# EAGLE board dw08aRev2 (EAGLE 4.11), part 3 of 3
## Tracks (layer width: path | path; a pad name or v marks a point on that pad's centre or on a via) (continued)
I_MB03  (via drill 0.61) (continued)
  Bottom 0.152: v220.09,95.89 221.23,95.89 235.97,110.62 237.36,110.62 239.01,112.27 A06.J1 | v285.75,52.2 285.75,52.96 v306.58,73.79 | v303.53,96.9 303.53,97.03 v306.58,100.08 | v292.61,114.05 292.1,114.05 291.21,113.16 A02.J1 | v267.59,138.68 268.86,139.95 266.32,142.49 253.49,142.49 249.81,138.81 249.81,138.18 242.19,130.56 240.92,130.56 224.16,113.79 220.09,113.79 208.41,102.11 208.41,100.71 A08.N2
I_MB03\  (via drill 0.61)
  Top 0.152: v222.76,101.98 219.33,105.41 218.69,105.41 211.58,112.52 211.58,115.19 A08.H2 | v304.17,32 294.13,42.04 294.13,45.34 B02.H1 | v287.4,12.7 265.18,12.7 259.08,18.8 258.95,18.8 258.57,19.18 258.57,19.81 253.11,25.27 252.6,25.27 249.81,28.07 247.65,28.07 v247.4,28.32 | v243.84,28.32 243.21,28.32 v223.52,48.01 | v244.86,68.71 244.86,70.36 243.59,71.63 242.95,71.63 v234.82,79.76 | v231.39,79.76 224.16,87 224.16,88.27 v217.17,95.25 | v279.53,132.84 293.24,119.13 293.24,116.59 A02.H1
  Bottom 0.152: v304.17,32 304.17,30.86 304.42,30.61 304.42,29.72 v287.4,12.7 | v243.84,28.32 v247.4,28.32 | v223.52,48.01 223.65,48.01 232.79,57.15 233.3,57.15 v244.86,68.71 | v234.82,79.76 v231.39,79.76 | v217.17,95.25 217.55,95.25 221.74,99.44 221.74,100.84 222.5,101.6 v222.76,101.98 226.82,101.98 235.84,111 236.35,111 239.14,113.79 239.78,113.79 242.19,116.2 A06.H1 243.59,116.33 245.24,117.98 246.63,117.98 252.98,124.33 259.33,124.33 260.86,125.86 262.76,125.86 269.75,132.84 v279.53,132.84
I_MB04  (via drill 0.61)
  Top 0.152: v298.45,42.8 298.45,43.69 284.1,58.04 284.1,58.17 283.46,58.8 283.46,59.56 283.08,59.94 283.08,61.34 279.91,64.52 279.91,65.02 276.61,68.33 276.1,68.33 260.86,83.57 260.86,85.85 260.22,86.49 260.22,87.5 v257.3,90.42 246.63,101.09 245.24,101.09 243.59,102.74 A06.M1 | v281.69,111.63 282.7,110.62 287.91,110.62 293.24,105.28 293.24,103.89 A02.M1 | v200.79,117.22 200.91,117.22 202.44,115.7 202.82,115.7 210.44,108.08 214.25,108.08 220.73,101.6 221.49,101.6 222.25,100.84 222.76,100.84 227.33,96.27 227.46,96.27 v229.74,93.98
  Bottom 0.152: v298.45,42.8 294.13,38.48 294.13,34.04 B02.M1 | v281.69,111.63 281.43,111.63 275.08,105.28 272.54,105.28 272.16,104.9 271.78,104.9 v257.3,90.42 | v200.79,117.22 199.9,116.33 199.14,116.33 A09.H2 | v229.74,93.98 230.89,93.98 236.09,99.19 237.24,99.19 239.14,101.09 240.54,101.09 242.19,102.74 A06.M1
I_MB04\  (via drill 0.61)
  Top 0.152: v213.23,83.44 212.98,83.69 211.84,83.69 A08.U2 | v227.08,95.5 235.97,86.61 236.35,86.61 250.06,72.9 251.33,72.9 261.62,62.61 263.02,62.61 264.03,61.59 264.03,61.34 288.42,36.96 289.81,36.96 B02.L1 | v296.93,114.3 296.93,116.2 296.55,116.59 296.55,116.97 v276.48,137.03 | v241.94,118.24 240.28,116.59 v244.47,112.39
  Bottom 0.152: v213.23,83.44 214.63,83.44 226.31,95.12 226.82,95.12 227.2,95.5 | 227.2,95.5 235.97,104.27 237.36,104.27 239.01,105.92 A06.L1 240.16,107.06 241.81,108.71 241.81,110.11 244.09,112.39 v244.47,112.39 | 227.2,95.5 v227.08,95.5 | v296.93,114.3 296.8,114.3 290.96,108.46 290.96,107.06 A02.L1 | v276.48,137.03 265.18,137.03 264.67,136.53 260.86,136.53 253.11,128.78 252.48,128.78 v241.94,118.24
I_MB05  (via drill 0.61)
  Top 0.152: v215.14,69.47 200.91,83.69 199.14,83.69 A09.U2 | v240.92,92.33 241.05,92.33 A06.S1 | v230.5,81.79 251.33,60.96 251.33,60.83 v255.4,56.77 258.83,53.34 258.83,52.83 270.51,41.15 270.89,41.15 290.96,21.08 292.99,21.08 B02.S1 | v290.32,92.08 291.46,90.93 292.99,90.93 A02.S1
  Bottom 0.152: v215.14,69.47 218.06,69.47 230.38,81.79 | 230.38,81.79 v240.92,92.33 | 230.38,81.79 v230.5,81.79 | v290.32,92.08 290.32,91.69 v255.4,56.77
I_MB05\  (via drill 0.61)
  Top 0.152: v277.75,45.85 285.12,38.48 285.12,37.85 293.24,29.72 293.24,27.69 B02.P1 | v282.57,52.32 282.57,53.59 264.16,72.01 | 264.16,72.01 257.05,79.12 255.78,79.12 255.14,79.76 255.14,80.64 249.68,86.11 249.68,87.12 250.32,87.76 244.98,93.09 244.98,94.49 243.33,96.14 A06.P1 | v292.1,100.33 293.24,99.19 293.24,97.54 A02.P1 | v264.16,71.37 264.16,72.01 | v194.56,96.77 194.56,96.01 209.04,81.53 209.04,79.63 209.8,78.87 216.53,78.87 v227.58,67.82 | v242.44,81.79 242.95,81.79 248.16,76.58 251.08,76.58 259.08,68.58 259.08,67.82 v259.84,67.06
  Bottom 0.152: v277.75,45.85 277.75,47.5 v282.57,52.32 | v292.1,100.33 292.1,99.69 288.67,96.27 288.67,95.38 265.94,72.64 265.43,72.64 v264.16,71.37 264.03,70.99 260.1,67.06 v259.84,67.06 | v194.56,96.77 194.82,97.03 194.82,99.31 A09.N2 | v227.58,67.82 227.71,67.82 232.28,72.39 232.28,72.77 233.55,74.04 234.7,74.04 v242.44,81.79
I_MB06  (via drill 0.61)
  Top 0.152: v197.87,86.11 196.34,87.63 196.34,87.88 184.66,99.57 183.26,99.57 A10.N2 | v250.44,86.49 256.03,80.9 256.29,80.9 284.23,52.96 286.13,52.96 286.26,52.83 286.64,52.83 B02.E2 | v267.46,140.21 267.72,140.21 283.59,124.33 284.99,124.33 286.64,122.68 A02.E2
  Bottom 0.152: v197.87,86.11 218.69,106.93 219.07,106.93 221.62,109.47 222.12,109.47 232.79,120.14 234.19,120.14 235.84,121.79 A06.E2 236.98,122.94 236.98,124.33 242.32,129.67 246,129.67 249.81,133.48 250.06,133.48 250.95,134.37 252.35,134.37 255.65,137.67 263.52,137.67 263.91,138.05 265.3,138.05 v267.46,140.21 | v250.44,86.49 250.44,87 260.99,97.54 260.99,98.3 266.32,103.63 266.57,103.63 272.42,109.47 272.92,109.47 283.59,120.14 284.99,120.14 286.64,121.79 A02.E2
I_MB06\  (via drill 0.61)
  Top 0.152: v196.85,103.12 186.18,113.79 186.18,115.19 A10.H2 | v224.28,131.19 225.43,131.19 226.31,130.3 226.82,130.3 229.62,127.51 231.01,127.51 232.66,125.86 A06.D2 | v280.54,62.74 281.43,61.85 281.43,61.34 282.07,60.71 282.07,59.69 283.72,58.04 283.72,56.26 B02.D2 | v305.94,95.25 305.94,95.63 v300.99,100.58 | v303.78,104.14 292.61,115.32 292.61,118.62 287.91,123.32 286.51,123.32 284.86,124.97 A02.D2 283.72,126.11 282.07,127.76 282.07,129.16 270.26,140.97 v266.45,140.97 | v249.05,138.56 v252.98,138.56
  Bottom 0.152: v196.85,103.12 196.85,103.76 v224.28,131.19 | v280.54,62.74 280.54,62.99 282.07,64.52 282.07,64.9 293.24,76.07 293.62,76.07 304.29,86.74 304.29,93.6 v305.94,95.25 | v300.99,100.58 300.99,101.35 v303.78,104.14 | v249.05,138.56 241.43,130.94 240.79,130.94 235.71,125.86 234.06,125.86 A06.D2 | v252.98,138.56 264.03,138.56 v266.45,140.97
I_MB07  (via drill 0.61)
  Top 0.152: v241.17,114.05 233.55,121.67 232.41,121.67 224.41,129.67 224.03,129.67 223.52,130.18 223.52,130.56 218.06,136.02 216.92,136.02 216.15,135.25 215.14,136.27 213.87,136.27 v209.42,140.72 | v285.88,38.35 285.88,38.86 276.61,48.13 276.35,48.13 v262.64,61.85 | v297.43,97.54 297.43,97.79 289.43,105.79 289.43,107.19 287.78,108.84 A02.K2 | v242.32,106.17 239.4,109.09 237.24,109.09 A06.K2 | v268.22,130.18 268.22,132.21 263.52,136.91 263.52,137.67 266.06,140.21 266.83,139.45 267.97,139.45 283.46,123.95 283.72,123.95 v290.96,116.71
  Bottom 0.152: v241.17,114.05 240.79,113.67 240.79,112.14 238.63,109.98 237.24,109.98 A06.K2 | v209.42,140.72 200.79,140.72 199.52,139.45 198.88,139.45 179.2,119.76 178.56,119.76 176.78,117.98 175.39,117.98 173.74,116.33 A11.H2 | v285.88,38.35 286.64,39.12 286.77,39.12 B02.K2 | v262.64,61.85 262.64,62.74 v297.43,97.54 | v242.32,106.17 243.46,106.17 249.81,112.52 250.57,112.52 v268.22,130.18 | v290.96,116.71 290.96,114.81 289.43,113.28 289.43,111.89 287.78,110.24 A02.K2
I_MB07\  (via drill 0.61)
  Top 0.152: v192.15,81.53 189.99,83.69 186.44,83.69 A10.U2 | v223.14,112.14 224.03,112.14 v227.58,108.58 | v255.91,80.14 256.54,79.5 257.18,79.5 286.89,49.78 286.89,46.74 B02.H2 | v231.27,112.27 231.52,112.27 v259.46,84.33
  Bottom 0.152: v192.15,81.53 197.49,86.87 198.12,86.87 221.49,110.24 221.49,110.49 v223.14,112.14 | v227.58,108.58 v231.27,112.27 232.79,113.79 234.19,113.79 235.84,115.44 A06.H2 | v255.91,80.14 255.91,80.64 259.59,84.33 | 259.59,84.33 272.92,97.66 272.92,99.06 284.1,110.24 284.1,111 285.24,112.14 285.24,113.54 286.89,115.19 A02.H2 | v259.46,84.33 259.59,84.33
I_MB08  (via drill 0.61)
  Top 0.152: v286.89,29.59 286.89,31.5 v265.81,52.58 | v294.26,81.03 294.26,81.28 293.62,81.92 293.62,82.55 286.26,89.92 286.26,93.09 v285.75,93.6 | v191.39,100.33 191.39,101.09 v190.63,101.85 | v209.93,123.32 211.84,123.32 217.3,117.86 219.46,117.86 229.24,108.08 229.24,107.57 230,106.81 230,105.03 234.44,100.58 234.44,99.19 236.09,97.54 A06.P2 | v263.91,1.27 237.24,1.27 v229.11,9.4 | v219.46,1.27 217.42,3.3 216.79,3.3 215.65,4.45 213.74,4.45 208.91,9.27 208.15,9.27 203.71,13.72 203.71,17.91 v190.37,31.24 | v196.22,41.53 196.22,42.16 196.34,42.29 196.34,45.21 195.2,46.35 194.56,46.35 v165.99,74.93
  Bottom 0.152: v286.89,29.59 286.89,27.69 B02.P2 286.64,26.54 283.85,26.54 262.89,5.59 262.89,2.29 v263.91,1.27 | v265.81,52.58 v294.26,81.03 | v285.75,93.6 285.75,95 286.89,96.14 A02.P2 | v191.39,100.33 175.64,84.58 173.74,84.58 A11.U2 172.59,83.44 170.94,81.79 170.94,80.39 165.99,75.44 v165.99,74.93 | v190.63,101.85 192.41,101.85 209.04,118.49 209.04,122.43 v209.93,123.32 | v229.11,9.4 227.58,9.4 v219.46,1.27 | v190.37,31.24 190.37,35.69 v196.22,41.53
I_MB08\  (via drill 0.61)
  Top 0.152: v276.23,47.37 276.86,46.74 276.86,45.59 286.89,35.56 286.89,34.04 B02.M2 | v288.16,60.71 268.22,80.64 268.22,81.41 268.73,81.92 269.24,81.92 269.75,81.41 269.75,81.03 270.89,79.88 273.05,79.88 274.19,81.03 270.89,84.33 270.26,84.33 v268.61,85.98 268.22,85.85 263.78,85.85 v261.62,88.01 | v203.2,129.79 208.28,129.79 232.79,105.28 234.19,105.28 235.84,103.63 A06.M2 237.24,102.74 237.74,102.23 v238.38,102.23 | v263.52,90.42 263.52,90.81 263.02,91.31 263.02,92.46 258.19,97.28 258.19,97.79 249.43,106.55 247.78,106.55 v246.38,107.95
  Bottom 0.152: v276.23,47.37 276.23,49.28 286.77,59.82 287.27,59.82 v288.16,60.71 | v268.61,85.98 268.61,86.11 274.07,91.57 275.21,91.57 276.73,93.09 276.73,94.23 283.59,101.09 284.99,101.09 286.64,102.74 A02.M2 | v203.2,129.79 173.86,100.46 170.56,100.46 A11.N2 | v261.62,88.01 261.62,88.52 v263.52,90.42 | v246.38,107.95 245.75,107.95 243.59,105.79 243.08,105.79 242.7,105.41 241.55,105.41 v238.38,102.23
I_MB09  (via drill 0.61)
  Top 0.152: v217.55,71.88 212.34,77.09 208.03,77.09 181.23,103.89 180.34,103.89 178.94,105.28 175.64,105.28 173.74,107.19 172.47,107.19 165.23,114.43 163.58,114.43 162.56,115.44 161.04,115.44 A12.H2 | v284.61,19.56 280.42,19.56 248.16,51.82 248.16,52.32 247.27,53.21 | 247.27,53.21 246.38,53.21 246.13,53.47 245.49,53.47 224.28,74.68 224.28,75.31 v223.52,76.07 | 247.27,53.21 v247.27,53.98
  Bottom 0.152: v217.55,71.88 219.58,71.88 223.65,75.95 | 223.65,75.95 229.74,82.04 229.74,82.17 230.63,83.06 230.76,83.06 234.44,86.74 234.44,88.14 236.09,89.79 A06.S2 | v284.61,19.56 285.24,20.19 286.64,20.19 B02.S2 | 223.65,75.95 v223.52,76.07 | v247.27,53.98 259.59,66.29 260.22,66.29 283.97,90.04 286.64,90.04 A02.S2
I_MB10  (via drill 0.61)
  Top 0.152: v160.91,98.42 160.53,98.81 159.51,98.81 158.75,99.57 157.86,99.57 A12.N2 | v184.02,113.79 v220.73,77.09 221.11,77.34 245.36,53.09 246,53.09 246.25,52.83 246.38,52.83 v246.89,52.32 281.31,17.91 283.46,17.91 B02.T2
  Bottom 0.152: v160.91,98.42 165.61,98.42 165.86,98.68 166.12,98.68 176.53,109.09 177.29,109.09 181.99,113.79 v184.02,113.79 | v220.73,77.09 220.73,77.34 221.36,77.98 221.36,78.61 228.22,85.47 231.27,85.47 232.66,86.87 A06.T2 | v246.89,52.32 282.07,87.5 283.46,87.5 A02.T2
I_MB11  (via drill 0.61)
  Top 0.152: 267.21,45.47 290.96,21.72 294.26,21.72 296.04,19.94 296.04,18.29 289.31,11.56 284.86,11.56 B02.V2 | 267.21,45.47 267.21,49.91 233.55,83.57 232.79,83.57 231.9,82.68 | 231.9,82.68 232.92,81.66 A06.V2 | v189.48,58.55 187.2,60.83 181.99,60.83 160.78,82.04 160.78,83.44 A12.U2 | v224.92,87.38 224.92,87.25 228.22,83.95 228.73,83.95 229.62,83.06 231.52,83.06 231.9,82.68 | v259.59,53.21 259.59,53.09 267.21,45.47
  Bottom 0.152: v189.48,58.55 190.25,58.55 194.69,62.99 199.52,62.99 202.82,66.29 203.84,66.29 v224.92,87.38 | v259.59,53.21 259.71,53.21 280.04,73.53 280.04,74.17 282.45,76.58 282.45,77.09 284.35,78.99 284.35,80.26 A02.V2
I_MBINCR  (via drill 0.61)
  Top 0.152: v65.15,61.59 67.82,58.93 67.82,56.26 B19.D2 | v142.24,138.05 161.04,138.05 165.86,133.22 166.75,133.22 172.47,127.51 178.31,127.51 194.56,111.25 195.07,111.25 203.45,102.87 203.45,102.23 223.01,82.68 223.01,82.42 231.52,73.91 232.28,73.91 233.17,74.8 v232.03,75.95 231.65,76.2 230.25,77.6 229.49,77.6 228.09,78.99 228.09,81.53 225.43,84.2 v225.43,84.33 | v247.14,89.15 247.78,89.15 v249.17,87.76 | v255.14,93.73 255.65,93.73 v260.1,89.28 | v243.59,2.79 240.66,2.79 v233.93,9.53 | v224.03,2.03 219.33,2.03 v209.17,12.19 | v199.01,1.91 197.74,1.91 197.61,2.03 196.47,2.03 188.47,10.03 188.34,10.03 176.91,21.46 176.91,21.59 175.77,22.73 175.64,22.73 v173.35,25.02 | v190.12,44.58 190.12,45.34 v189.36,46.1
  Bottom 0.152: v65.15,61.59 65.41,61.59 69.72,65.91 69.72,66.55 113.92,110.74 114.94,110.74 v142.24,138.05 | v232.03,75.95 232.28,75.95 235.08,78.74 235.84,78.74 242.32,85.22 242.57,85.22 243.08,85.72 243.08,85.98 245.49,88.39 246.38,88.39 v247.14,89.15 | v249.17,87.76 v255.14,93.73 | v260.1,89.28 260.1,88.9 259.21,88.01 A04.T2 | v243.59,2.79 251.33,10.54 251.33,11.68 256.67,17.02 258.06,17.02 B04.T2 | v233.93,9.53 231.52,9.53 v224.03,2.03 | v209.17,12.19 207.39,12.19 206.88,11.68 206.88,9.91 199.01,2.03 v199.01,1.91 | v173.35,25.02 173.35,25.65 189.99,42.29 189.99,44.45 v190.12,44.58 | v189.36,46.1 189.99,46.1 194.56,50.67 195.07,50.67 197.87,53.47 201.17,53.47 209.04,61.34 209.04,67.94 220.22,79.12 220.47,79.12 224.92,83.57 224.92,83.82 v225.43,84.33
I_RUN  (via drill 0.61)
  Top 0.152: v273.18,21.97 273.94,21.21 273.94,21.08 B03.S2 | v258.57,7.62 254.25,7.62 249.94,11.94 249.94,12.06 249.56,12.45 248.92,12.45 241.17,20.19 241.17,20.7 225.93,35.94 225.93,37.34 224.28,38.99 B07.K2 223.14,40.13 221.49,41.78 220.09,41.78 218.95,42.93 v220.47,44.45 | v164.21,73.53 166.24,73.53 v185.29,54.48 | v199.77,57.4 199.77,55.75 220.09,35.43 221.23,35.43 222.12,36.32 221.87,36.58 221.87,37.72 v221.74,37.85 | v272.92,88.27 272.92,87.63 v274.83,85.72 | v257.18,65.28 257.05,65.28 256.16,66.17 254.13,66.17 v249.56,70.74
  Bottom 0.152: v273.18,21.97 269.75,18.54 269.11,18.54 259.33,8.76 259.33,8.38 v258.57,7.62 | v164.21,73.53 155.45,64.77 155.45,64.39 137.54,46.48 135.64,46.48 B14.H2 | v185.29,54.48 192.53,54.48 194.69,56.64 197.61,56.64 198.37,57.4 v199.77,57.4 | v221.74,37.85 223.14,39.24 B07.K2 | v272.92,88.27 274.19,89.53 274.19,89.79 A03.S2 | v274.83,85.72 274.57,85.72 270.38,81.53 270.38,78.99 269.11,77.72 268.48,77.72 259.46,68.71 259.46,67.82 259.08,67.44 259.08,67.18 v257.18,65.28 | v249.56,70.74 249.56,70.1 237.11,57.66 234.31,57.66 233.43,56.77 232.92,56.77 225.93,49.78 225.93,49.28 223.9,47.24 223.27,47.24 v220.47,44.45
I_SKIP  (via drill 0.61)
  Top 0.152: v104.52,35.05 84.45,55.12 81.66,55.12 B18.D2 | v125.09,51.05 127.76,51.05 127.89,50.93 128.4,50.93 147.07,32.26 151.64,32.26 v151.76,32.13 | v162.43,38.48 172.09,38.48 172.34,38.23 172.72,38.23 197.74,13.21 200.41,13.21 v200.66,12.95 | v210.57,22.23 211.2,22.23 v231.01,2.41 | v255.02,25.02 255.91,25.02 258.19,22.73 259.59,22.73 v259.84,22.48 | v266.7,102.87 265.81,102.87 258.19,110.49 258.19,111.38 v252.86,116.71 | v254,119 254,125.98 243.59,136.4 242.32,136.4 241.94,136.78 241.94,137.03 v236.73,142.24 | v201.42,103.63 201.42,101.85 v213.74,89.53
  Bottom 0.152: v104.52,35.05 109.09,35.05 v125.09,51.05 | v151.76,32.13 156.08,32.13 v162.43,38.48 162.69,38.86 171.45,47.62 171.45,48.39 187.83,64.77 188.34,64.77 211.58,88.01 212.22,88.01 v213.74,89.53 | v200.66,12.95 201.29,12.95 v210.57,22.23 | v231.01,2.41 233.81,2.41 243.71,12.32 243.71,13.46 247.14,16.89 247.14,17.27 248.16,18.29 248.54,18.29 253.49,23.24 253.49,23.5 v255.02,25.02 | v259.84,22.48 265.18,27.81 265.18,28.57 272.54,35.94 272.54,37.34 274.19,38.99 B03.K2 | v266.7,102.87 267.21,103.38 267.21,103.76 272.54,109.09 273.94,109.09 A03.K2 | v252.86,116.71 252.86,117.86 v254,119 | v236.73,142.24 235.33,142.24 228.47,135.38 228.47,134.87 225.93,132.33 225.93,131.06 224.66,129.79 223.39,129.79 203.71,110.11 203.71,105.92 v201.42,103.63
I_TS1  (via drill 0.61)
  Top 0.152: v242.7,35.05 241.68,36.07 240.41,36.07 B06.L1 | v263.4,55.63 265.68,53.34 266.19,53.34 267.21,52.32 267.21,51.82 294.51,24.51 294.51,23.62 296.42,21.72 296.42,18.16 B01.T2
  Bottom 0.152: v242.7,35.05 242.7,35.69 246.25,39.24 246.63,39.24 259.84,52.45 259.97,52.45 260.35,52.83 260.35,53.34 263.02,56.01 | 263.02,56.01 268.1,61.09 268.61,61.09 275.84,68.33 276.48,68.33 286.77,78.61 286.77,78.87 293.12,85.22 294.51,85.22 296.16,86.87 A01.T2 | 263.02,56.01 v263.4,55.63
I_TS3  (via drill 0.61)
  Top 0.152: v292.23,16.38 288.93,16.38 271.65,33.66 271.4,33.66 264.67,40.39 263.65,40.39 256.29,47.75 255.52,47.75 252.98,50.29 v251.08,50.29 | v241.68,42.29 240.54,42.29 240.41,42.42 B06.J1 | v293.75,95 297.81,90.93 299.34,90.93 A01.S2
  Bottom 0.152: v292.23,16.38 296.04,20.19 299.34,20.19 B01.S2 | v241.68,42.29 244.47,45.09 245.87,45.09 v251.08,50.29 251.46,50.55 261.87,60.96 261.87,62.23 262.25,62.61 262.25,62.87 293.75,94.36 v293.75,95
I_TT_INST  (via drill 0.61)
  Top 0.152: v148.84,44.45 152.78,44.45 v170.31,26.92 | v196.85,50.67 197.36,50.67 v198.75,49.28 v216.79,31.24 | v269.37,19.3 270.76,17.91 B03.T2 | v256.67,6.86 252.86,6.86 248.41,11.3 248.41,11.68 234.19,25.91 233.43,25.91 227.58,31.75 226.57,31.75 224.54,33.78 B07.M2 | v247.4,63.75 247.14,63.75 v232.92,77.98
  Bottom 0.152: v148.84,44.45 143.26,38.86 142.11,38.86 133.86,30.61 132.46,30.61 B14.N2 | v170.31,26.92 171.32,26.92 194.69,50.29 196.47,50.29 v196.85,50.67 | v216.79,31.24 221.49,31.24 223.14,32.89 B07.M2 | v269.37,19.3 269.11,19.3 v256.67,6.86 | v247.4,63.75 247.65,64.01 249.81,64.01 259.84,74.04 259.84,74.68 265.05,79.88 265.68,79.88 267.97,82.17 267.21,82.93 267.21,84.71 267.72,85.22 268.99,85.22 270.64,86.87 270.76,86.87 A03.T2 | v232.92,77.98 229.49,77.98 225.55,74.04 224.79,74.04 215.9,65.15 214.63,65.15 v198.75,49.28
I_WCOV  (via drill 0.61)
  Top 0.152: v236.85,3.17 223.01,17.02 221.36,17.02 B07.T2 | v254.51,22.23 254.51,23.37 252.98,24.89 251.59,24.89 249.94,26.54 B05.P2 | v137.41,13.21 136.02,14.61 136.02,14.86 121.16,29.72 119.76,29.72 B15.N2 | v183.64,45.34 183.64,44.7 199.26,29.08 201.04,29.08 204.22,25.91 204.47,25.91 206.25,24.13 206.25,23.88 210.57,19.56 210.82,19.56 212.6,17.78 212.6,16.13 v215.14,13.59 | v230.5,114.3 232.28,112.52 232.28,112.14 247.14,97.28 248.54,97.28 A05.P2 | v195.83,75.56 195.83,74.04 v199.26,70.61
  Bottom 0.152: v236.85,3.17 240.54,3.17 245.11,7.75 245.11,8.51 247.14,10.54 247.14,10.79 248.79,12.45 249.05,12.45 253.49,16.89 253.49,18.41 254.38,19.3 254.38,22.1 v254.51,22.23 | v137.41,13.21 144.4,13.21 159.64,28.45 160.15,28.45 174.75,43.05 | 174.75,43.05 175.64,43.94 182.25,43.94 v183.64,45.34 | v215.14,13.59 216.92,15.37 218.31,15.37 219.96,17.02 B07.T2 | v230.5,114.3 230.5,113.67 214.12,97.28 214.12,96.9 213.74,96.52 213.74,94.74 200.53,81.53 200.53,80.26 v195.83,75.56 | v199.26,70.61 189.48,60.83 189.23,60.83 188.59,60.2 188.59,59.18 174.75,45.34 174.75,43.05
N$1  (via drill 0.61)
  Top 0.152: v213.49,47.5 v217.17,43.81 | v237.49,63.63 237.74,63.63 239.01,62.36 B06.B1
  Bottom 0.152: v213.49,47.5 212.47,46.48 211.84,46.48 B08.H2 | v217.17,43.81 217.68,43.81 v237.49,63.63
N$2  (via drill 0.61)
  Top 0.152: v210.19,29.21 209.68,29.72 208.66,29.72 B08.N2 | v237.62,56.01 239.14,54.48 240.54,54.48 242.19,52.83 B06.E1
  Bottom 0.152: v210.19,29.21 210.82,29.21 v237.62,56.01
N$3  (via drill 0.61)
  Top 0.152: v240.92,47.5 241.17,47.5 242.19,46.48 B06.H1
  Bottom 0.152: v240.92,47.5 240.79,47.5 210.69,17.4 211.46,16.64 211.58,16.64 211.96,16.26 211.96,15.49 211.58,15.11 211.58,14.99 B08.U2
N$4  (via drill 0.61)
  Top 0.152: v217.55,60.33 221.36,56.52 224.92,56.52 225.93,55.5 225.93,54.99 240.79,40.13 242.19,40.13 B06.K1
  Bottom 0.152: v217.55,60.33 214.38,60.33 202.18,48.13 200.79,48.13 199.14,46.48 B09.H2
N$5  (via drill 0.61)
  Top 0.152: v216.92,7.87 215.14,9.65 213.61,9.65 195.71,27.56 195.71,29.46 B09.N2
  Bottom 0.152: v216.92,7.87 220.22,7.87 240.54,28.19 240.54,29.34 240.79,29.59 240.79,30.99 242.44,32.64 B06.M1
N$6  (via drill 0.61)
  Top 0.152: v213.49,2.92 v200.28,16.13
  Bottom 0.152: v213.49,2.92 215.77,2.92 216.53,3.68 216.92,3.68 226.19,12.95 227.2,12.95 232.79,18.54 236.09,18.54 240.79,23.24 240.79,24.64 242.44,26.29 B06.P1 | v200.28,16.13 B09.U2
O_3CYCLE
  Top 0.152: B19.H2 70.99,46.74 70.99,50.67 63.63,58.04 63.63,63.37 62.87,64.14 62.87,65.15 47.75,80.26 47.75,80.77 32.26,96.27 32.26,108.2 32.89,108.84 A22.K2
O_AC00  (via drill 0.61)
  Top 0.152: v118.75,65.79 118.75,66.42 104.65,80.52 104.65,81.03 104.27,81.41 104.27,85.85 103.5,86.61 103.5,88.52 102.11,89.92 102.11,102.62 92.58,112.14 92.58,119.89 92.46,120.02 92.46,123.95 93.22,124.71 A17.D2
  Bottom 0.152: v118.75,65.79 109.22,56.26 109.22,53.09 B16.E2
O_AC01  (via drill 0.61)
  Top 0.152: v91.69,72.01 98.3,65.41 98.3,64.52 98.55,64.26 98.55,61.21 105.79,53.98 105.79,53.09 109.09,49.78 109.09,46.74 B16.H2 | v104.27,87 104.27,106.81 95.76,115.32 95.76,120.9 96.39,121.54 A17.E2
  Bottom 0.152: v91.69,72.01 91.69,74.42 v104.27,87
O_AC02  (via drill 0.61)
  Top 0.152: v109.35,43.43 109.35,40.39 B16.K2 | v136.91,73.53 136.91,74.42 131.95,79.38 131.7,79.38 127.51,83.57 127.51,86.87 100.58,113.79 99.19,113.79 97.54,115.44 A17.H2
  Bottom 0.152: v109.35,43.43 109.35,43.69 117.35,51.69 117.35,52.2 129.67,64.52 129.67,66.29 v136.91,73.53
O_AC03  (via drill 0.61)
  Top 0.152: v69.09,82.8 82.68,69.22 82.68,68.07 83.06,67.69 83.19,67.69 91.82,59.05 91.82,57.78 92.2,57.4 92.2,48.51 106.93,33.78 108.84,33.78 B16.M2
  Bottom 0.152: v69.09,82.8 71.75,82.8 94.74,105.79 94.74,107.19 96.39,108.84 A17.K2
O_AC04  (via drill 0.61)
  Top 0.152: v125.73,46.61 125.73,47.24 124.33,48.64 124.33,54.99 116.59,62.74 116.33,62.74 103.25,75.82 103.25,81.28 v90.81,93.73
  Bottom 0.152: v125.73,46.61 109.98,30.86 109.98,27.69 B16.P2 | v90.81,93.73 90.81,95.5 94.74,99.44 94.74,100.84 96.39,102.49 A17.M2
O_AC05  (via drill 0.61)
  Top 0.152: v121.67,34.92 121.67,37.72 109.86,49.53 109.86,50.42 98.93,61.34 98.93,64.39 98.68,64.64 98.68,66.67 v83.44,81.92
  Bottom 0.152: v121.67,34.92 109.98,23.24 109.98,21.34 B16.S2 | v83.44,81.92 83.57,81.92 94.74,93.09 94.74,94.49 96.39,96.14 A17.P2
O_AC06  (via drill 0.61)
  Top 0.152: v96.14,54.48 96.39,54.23 96.39,53.09 B17.E2 | v104.52,62.87 104.52,65.91 v90.3,80.14
  Bottom 0.152: v96.14,54.48 v104.52,62.87 | v90.3,80.14 90.3,81.79 91.95,83.44 91.95,83.95 94.74,86.74 94.74,88.14 96.39,89.79 A17.S2
O_AC07  (via drill 0.61)
  Top 0.152: v103.12,53.98 103.12,54.99 87.5,70.61 87.5,73.91 v85.72,75.69
  Bottom 0.152: v103.12,53.98 97.28,48.13 97.28,46.74 B17.H2 | v85.72,75.69 85.72,77.72 91.57,83.57 91.57,84.96 93.22,86.61 A17.T2
O_AC08  (via drill 0.61)
  Top 0.152: v101.6,46.86 101.6,50.29 v83.44,68.45
  Bottom 0.152: v101.6,46.86 97.28,42.55 97.28,40.39 B17.K2 | v83.44,68.45 83.44,70.48 93.22,80.26 A17.V2
O_AC09  (via drill 0.61)
  Top 0.152: v53.34,94.23 56.64,90.93 56.64,87.76 57.28,87.12 57.28,83.44 76.33,64.39 76.33,58.04 78.36,56.01 78.36,54.1 93.73,38.73 93.73,38.1 95.38,36.45 95.38,35.94 96.39,34.92 96.39,34.04 B17.M2
  Bottom 0.152: v53.34,94.23 53.34,95.63 69.72,112.01 69.72,112.52 78.87,121.67 78.87,123.06 80.52,124.71 A18.D2
O_AC10  (via drill 0.61)
  Top 0.152: v48.13,83.82 48.13,80.39 63.25,65.28 63.25,64.26 64.39,63.12 64.39,61.21 67.18,58.42 67.18,54.99 76.33,45.85 76.33,45.34 79.12,42.55 79.12,42.04 93.73,27.43 96.14,27.43 B17.P2
  Bottom 0.152: v48.13,83.82 54.1,89.79 54.1,90.55 82.04,118.49 82.04,119.76 83.82,121.54 A18.E2
O_AC11  (via drill 0.61)
  Top 0.152: v80.77,39.24 96.39,23.62 96.39,21.34 B17.S2 | v86.74,46.86 86.11,46.86 78.74,54.23 78.74,56.13 76.71,58.17 76.71,64.52 57.66,83.57 57.66,87.88 v57.4,88.14
  Bottom 0.152: v80.77,39.24 80.77,40.89 v86.74,46.86 | v57.4,88.14 57.4,90.81 80.39,113.79 81.79,113.79 83.44,115.44 A18.H2
O_ACCEPT  (via drill 0.61)
  Top 0.152: v108.08,44.96 62.99,90.04 59.44,90.04 A20.S2
  Bottom 0.152: v108.08,44.96 110.11,44.96 116.97,51.82 116.97,53.21 118.62,54.86 B15.D2
O_ACCLR  (via drill 0.61)
  Top 0.152: v77.85,48.64 79.88,46.61 79.88,42.29 82.04,40.13 83.44,40.13 B18.K2 | v102.36,73.41 102.36,76.96 86.23,93.09 86.23,94.49 84.58,96.14 A18.P2
  Bottom 0.152: v77.85,48.64 77.85,49.4 93.47,65.02 93.85,65.02 102.23,73.41 v102.36,73.41
O_ADD00  (via drill 0.61)
  Top 0.152: v31.11,84.71 54.48,61.34 54.48,54.99 56.64,52.83 58.04,52.83 B20.E2
  Bottom 0.152: v31.11,84.71 31.11,86.11 44.32,99.31 44.32,99.82 66.17,121.67 66.17,123.06 67.82,124.71 A19.D2
O_ADD01  (via drill 0.61)
  Top 0.152: v35.31,79.38 54.1,60.58 54.1,54.86 54.48,54.48 54.48,48.64 56.64,46.48 58.04,46.48 B20.H2
  Bottom 0.152: v35.31,79.38 35.31,83.19 42.8,90.68 42.8,91.44 47.5,96.14 47.5,96.65 69.34,118.49 69.34,119.76 71.12,121.54 A19.E2
O_ADD02  (via drill 0.61)
  Top 0.152: v32.26,73.28 38.61,66.93 38.61,64.52 53.72,49.4 53.72,48.39 58.29,43.81 58.29,40.39 B20.K2
  Bottom 0.152: v32.26,73.28 32.26,74.04 41.53,83.31 41.53,83.82 44.32,86.61 44.32,87.12 69.34,112.14 69.34,113.54 70.99,115.19 A19.H2
O_ADD03  (via drill 0.61)
  Top 0.152: v28.07,67.82 28.07,64.52 29.08,63.5 29.08,61.34 56.64,33.78 58.04,33.78 B20.M2
  Bottom 0.152: v28.07,67.82 67.69,107.44 69.09,107.44 70.74,109.09 A19.K2
O_ADD04  (via drill 0.61)
  Top 0.152: v88.27,70.99 88.27,74.3 86.11,76.45 86.11,77.6 82.3,81.41 82.3,83.82 81.92,84.2 81.92,84.71 79.88,86.74 79.88,93.09 73.53,99.44 73.53,100.84 71.88,102.49 A19.M2
  Bottom 0.152: v88.27,70.99 83.82,66.55 83.44,66.55 60.83,43.94 54.99,43.94 47.12,36.07 47.12,32.77 44.83,30.48 49.4,25.91 52.96,25.91 53.59,26.54 58.04,26.54 B20.P2
O_ADD05  (via drill 0.61)
  Top 0.152: v60.2,26.16 60.2,29.08 v32.89,56.39
  Bottom 0.152: v60.2,26.16 59.18,25.15 59.18,21.34 B20.S2 | v32.89,56.39 32.89,56.64 69.34,93.09 69.34,94.49 70.99,96.14 A19.P2
O_ADD06  (via drill 0.61)
  Top 0.152: v72.9,81.28 72.9,88.77 71.88,89.79 A19.S2
  Bottom 0.152: v72.9,81.28 63.5,71.88 63.5,67.69 62.36,66.55 58.04,66.55 52.32,60.83 51.56,60.83 49.66,58.93 48.39,58.93 46.1,56.64 42.29,56.64 41.78,56.13 41.78,56.01 41.27,55.5 43.94,52.83 45.34,52.83 B21.E2
O_ADD07  (via drill 0.61)
  Top 0.152: v38.99,55.12 45.59,48.51 45.59,46.74 B21.H2
  Bottom 0.152: v38.99,55.12 53.47,69.6 53.47,70.87 66.17,83.57 66.17,84.96 67.82,86.61 A19.T2
O_ADD08  (via drill 0.61)
  Top 0.152: v68.96,59.82 68.71,59.82 64.01,64.52 64.01,66.8 v62.74,68.07
  Bottom 0.152: v68.96,59.82 49.28,40.13 46.74,40.13 B21.K2 | v62.74,68.07 62.74,75.18 67.82,80.26 A19.V2
O_ADD09  (via drill 0.61)
  Top 0.152: v21.59,94.23 21.97,93.85 21.97,80.14 24.26,77.85 24.26,68.83 25.53,67.56 25.53,64.39 28.32,61.59 28.32,61.09 31.75,57.66 31.75,55.88 32.26,55.37 32.26,51.82 45.59,38.48 45.59,34.04 B21.M2
  Bottom 0.152: v21.59,94.23 22.23,94.23 42.16,114.17 42.67,114.17 51.82,123.32 53.21,123.32 54.86,124.97 A20.D2
O_ADD10  (via drill 0.61)
  Top 0.152: v20.32,80.26 23.88,76.71 23.88,68.71 24.51,68.07 24.51,64.39 31.24,57.66 31.24,55.63 31.88,54.99 31.88,51.69 44.96,38.61 44.96,32.77 50.42,27.3 49.66,26.54 46.74,26.54 B21.P2
  Bottom 0.152: v20.32,80.26 20.32,81.66 44.32,105.66 44.32,106.17 56.64,118.49 56.64,119.89 58.29,121.54 A20.E2
O_ADD11  (via drill 0.61)
  Top 0.152: v13.21,72.01 13.21,64.52 15.24,62.48 15.24,60.96 28.32,47.88 28.32,42.04 28.7,41.66 28.7,35.81 43.43,21.08 45.34,21.08 B21.S2
  Bottom 0.152: v13.21,72.01 54.99,113.79 56.39,113.79 58.04,115.44 A20.H2
O_BAC00  (via drill 0.61)
  Top 0.152: v149.35,120.02 148.72,120.65 148.72,122.81 147.57,123.95 147.07,123.95 146.05,124.97 145.16,124.97 A13.D2 | v133.35,103.25 133.35,103.12 158.12,78.36 158.24,78.36 171.96,64.64 171.96,64.52 178.82,57.66 180.21,57.66 181.86,56.01 B10.D2
  Bottom 0.152: v149.35,120.02 149.35,119.25 v133.35,103.25
O_BAC01  (via drill 0.61)
  Top 0.152: v183.39,78.99 182.5,79.88 181.99,79.88 174.12,87.76 174.12,91.06 169.29,95.89 168.28,95.89 167.77,96.39 167.77,97.41 165.99,99.19 165.99,100.46 165.48,100.97 165.48,103.25 163.45,105.28 162.94,105.28 148.08,120.14 148.08,121.54 A13.E2 | v169.93,65.53 169.93,63.63 171.83,61.72 172.85,61.72 v184.4,50.16 | v183.51,41.53 183.64,41.53 185.04,40.13 B10.K2
  Bottom 0.152: v183.39,78.99 v169.93,65.53 | v184.4,50.16 184.4,42.8 183.9,42.29 183.9,41.91 v183.51,41.53
O_BAC02  (via drill 0.61)
  Top 0.152: v143,115.95 146.94,115.95 A13.H2 | v117.47,91.57 131.19,77.85 131.44,77.85 136.53,72.77 136.91,72.77 164.47,45.21 164.47,43.56 164.59,43.43 164.59,41.78 161.29,38.48 162.05,37.72 166.12,37.72 170.18,33.66 170.56,33.66 175.51,28.7 176.02,28.7 181.99,22.73 183.39,22.73 185.04,21.08 B10.S2
  Bottom 0.152: v143,115.95 122.81,95.76 122.17,95.76 121.41,95 118.75,95 117.98,94.23 117.98,92.08 v117.47,91.57
O_BAC03  (via drill 0.61)
  Top 0.152: v137.03,95 137.03,92.2 164.97,64.26 164.97,62.1 167.77,59.31 167.77,57.91 169.42,56.26 B11.D2
  Bottom 0.152: v137.03,95 149.48,107.44 148.08,108.84 A13.K2
O_BAC04  (via drill 0.61)
  Top 0.152: v143.38,77.98 168.78,52.58 168.78,48.64 170.81,46.61 170.81,46.1 171.7,45.21 171.7,44.07 172.59,43.18 172.59,40.39 B11.K2 | v157.61,95.25 157.23,95.25 151.38,101.09 149.99,101.09 148.34,102.74 A13.M2
  Bottom 0.152: v143.38,77.98 143.38,81.53 156.59,94.74 157.1,94.74 v157.61,95.25
O_BAC05  (via drill 0.61)
  Top 0.152: v133.73,55.88 160.53,29.08 161.29,29.08 169.29,21.08 172.34,21.08 B11.S2 | v161.67,86.23 161.04,86.23 156.34,90.93 155.7,90.93 154.69,91.95 154.18,91.95 151.38,94.74 149.99,94.74 148.34,96.39 A13.P2
  Bottom 0.152: v133.73,55.88 136.02,58.17 136.02,59.31 136.4,59.69 137.54,59.69 161.42,83.57 161.42,85.98 v161.67,86.23
O_BAC06  (via drill 0.61)
  Top 0.152: v138.68,77.6 156.72,59.56 156.72,56.26 B12.D2
  Bottom 0.152: v138.68,77.6 138.68,79.38 142.75,83.44 142.75,83.95 145.54,86.74 145.54,88.14 147.19,89.79 A13.S2
O_BAC07  (via drill 0.61)
  Top 0.152: v131.83,70.87 136.53,66.17 136.53,65.02 137.03,64.52 137.03,61.34 157.35,41.02 157.86,41.02 158.75,40.13 159.64,40.13 B12.K2
  Bottom 0.152: v131.83,70.87 131.83,73.03 142.37,83.57 142.37,84.96 144.02,86.61 A13.T2
O_BAC08  (via drill 0.61)
  Top 0.152: v177.29,41.66 177.29,46.48 v144.91,78.87
  Bottom 0.152: v177.29,41.66 171.32,35.69 171.32,34.04 160.78,23.5 160.78,21.34 B12.S2 | v144.91,78.87 144.91,80.26 A13.V2
O_BAC09  (via drill 0.61)
  Top 0.152: v147.57,107.95 132.21,123.32 132.21,124.71 A14.D2 | v122.3,81.53 142.24,61.59 142.24,59.44 142.37,59.31 142.37,57.91 144.02,56.26 B13.D2
  Bottom 0.152: v147.57,107.95 147.57,106.81 v122.3,81.53
O_BAC10  (via drill 0.61)
  Top 0.152: v105.03,81.92 104.65,81.53 105.03,81.15 105.03,80.64 143.89,41.78 145.29,41.78 146.94,40.13 B13.K2
  Bottom 0.152: v105.03,81.92 120.65,97.54 120.65,103.76 126.24,109.35 126.24,110.24 134.49,118.49 134.49,121.54 A14.E2
O_BAC11  (via drill 0.61)
  Top 0.152: v135.25,37.72 147.19,25.78 147.19,21.34 B13.S2 | v152.27,60.07 152.27,62.74 130.18,84.84 130.18,86.61 v121.03,95.76
  Bottom 0.152: v135.25,37.72 135.25,38.35 145.54,48.64 145.54,53.34 v152.27,60.07 | v121.03,95.76 121.03,103.63 121.67,104.27 124.97,104.27 132.84,112.14 132.84,113.54 134.49,115.19 A14.H2
O_BREAK  (via drill 0.61)
  Top 0.152: v59.82,91.69 59.18,92.33 59.18,96.14 A20.P2 | v51.94,81.15 51.94,80.52 70.74,61.72 70.74,61.09 72.52,59.31 72.52,56.52 72.64,56.39 72.64,55.37 105.66,22.35 109.98,22.35 v121.92,10.41
  Bottom 0.152: v59.82,91.69 59.82,89.03 v51.94,81.15 | v121.92,10.41 123.06,10.41 131.19,18.54 132.59,18.54 134.24,20.19 B14.S2
O_BRKRQ  (via drill 0.61)
  Top 0.152: v90.55,31.75 89.92,31.75 79.5,42.16 79.5,42.67 76.71,45.47 76.71,50.42 72.26,54.86 72.26,56.26 70.36,58.17 70.36,61.59 51.18,80.77 51.18,81.92 v42.04,91.06
  Bottom 0.152: v90.55,31.75 86.23,27.43 84.84,27.43 B18.P2 | v42.04,91.06 42.04,91.19 47.12,96.27 47.12,99.57 54.99,107.44 56.39,107.44 58.04,109.09 A20.K2
O_CAINCR  (via drill 0.61)
  Top 0.152: v28.57,91.69 57.66,62.61 57.66,58.17 69.98,45.85 69.98,45.34 70.23,45.09 70.23,40.89 B19.K2
  Bottom 0.152: v28.57,91.69 28.57,96.77 31.24,99.44 31.24,100.84 32.89,102.49 A22.M2
O_DATA00  (via drill 0.61)
  Top 0.152: v21.97,106.17 22.35,105.79 22.35,80.26 24.64,77.98 24.64,68.96 25.91,67.69 25.91,64.52 28.7,61.72 28.7,61.21 32.13,57.78 32.13,56.01 32.89,55.24 32.89,53.09 B22.E2
  Bottom 0.152: v21.97,106.17 39.12,123.32 40.51,123.32 42.16,124.97 A21.D2
O_DATA01  (via drill 0.61)
  Top 0.152: v12.06,84.71 15.11,81.66 15.11,76.07 16.38,74.8 16.38,61.34 31.24,46.48 32.64,46.48 B22.H2
  Bottom 0.152: v12.06,84.71 12.06,86.61 43.94,118.49 43.94,119.76 45.72,121.54 A21.E2
O_DATA02  (via drill 0.61)
  Top 0.152: v13.21,77.47 16,74.68 16,61.21 29.08,48.13 29.08,42.29 31.24,40.13 32.64,40.13 B22.K2
  Bottom 0.152: v13.21,77.47 13.21,84.71 42.29,113.79 43.69,113.79 45.34,115.44 A21.H2
O_DATA03  (via drill 0.61)
  Top 0.152: v14.48,75.06 15.62,73.91 15.62,61.09 28.7,48.01 28.7,42.16 29.08,41.78 29.08,35.94 31.24,33.78 32.64,33.78 B22.M2
  Bottom 0.152: v14.48,75.06 14.48,76.33 43.94,105.79 43.94,107.19 45.59,108.84 A21.K2
O_DATA04  (via drill 0.61)
  Top 0.152: v8.26,61.59 28.32,41.53 28.32,35.69 32.89,31.11 32.89,27.69 B22.P2
  Bottom 0.152: v8.26,61.59 8.26,63.37 12.06,67.18 12.06,67.56 43.94,99.44 43.94,100.84 45.59,102.49 A21.M2
O_DATA05
  Bottom 0.152: B22.S2 32.64,21.08 28.32,21.08 19.18,30.23 18.03,29.08 16.76,29.08 1.52,44.32 5.84,48.64 5.84,54.99 9.02,58.17 9.02,61.47 42.29,94.74 43.69,94.74 45.34,96.39 A21.P2
O_DATA06
  Bottom 0.152: B23.E2 19.94,52.83 18.54,52.83 15.75,55.63 15.75,58.04 41.15,83.44 41.15,83.95 43.94,86.74 43.94,88.14 45.59,89.79 A21.S2
O_DATA07
  Bottom 0.152: B23.H2 19.94,46.48 18.54,46.48 14.35,50.67 15.37,51.69 15.37,58.17 40.77,83.57 40.77,84.96 42.42,86.61 A21.T2
O_DATA08  (via drill 0.61)
  Top 0.152: v47.5,74.42 47.5,76.07 43.31,80.26 A21.V2
  Bottom 0.152: v47.5,74.42 47.37,74.42 21.72,48.77 21.72,45.47 21.08,44.83 21.08,40.39 B23.K2
O_DATA09
  Top 0.152: B23.M2 20.19,34.04 20.19,38.48 19.56,39.12 19.56,49.15 7.49,61.21 7.49,63.88 6.86,64.52 6.86,116.59 21.84,131.57 23.11,130.3 23.62,130.3 26.42,127.51 27.81,127.51 29.46,125.86 A22.D2
O_DATA10  (via drill 0.61)
  Top 0.152: v6.1,92.71 6.48,92.33 6.48,64.39 6.86,64.01 6.86,58.17 19.18,45.85 19.18,38.99 19.56,38.61 19.56,32.77 20.19,32.13 20.19,27.69 B23.P2
  Bottom 0.152: v6.1,92.71 6.1,93.34 31.24,118.49 31.24,119.76 33.02,121.54 A22.E2
O_DATA11
  Bottom 0.152: B23.S2 20.19,21.34 20.19,25.15 0.76,44.58 0.76,81.66 31.24,112.14 31.24,113.54 32.89,115.19 A22.H2
O_DATAIN  (via drill 0.61)
  Top 0.152: v68.2,39.62 83.69,24.13 83.69,21.34 B18.S2 | v79.5,54.61 79.5,66.42 77.85,68.07 77.85,69.72 57.66,89.92 57.66,101.85 58.29,102.49 A20.M2
  Bottom 0.152: v68.2,39.62 68.2,41.15 78.87,51.82 78.87,53.98 v79.5,54.61
O_EXTA0  (via drill 0.61)
  Top 0.152: v70.99,25.4 70.87,25.4 66.8,29.46 66.8,29.97 57.66,39.12 57.66,43.94 53.34,48.26 53.34,49.28 38.23,64.39 38.23,66.17 31.5,72.9 31.5,83.19 30.35,84.33 30.35,85.47 22.73,93.09 22.73,113.54 21.08,115.19 A23.H2
  Bottom 0.152: v70.99,25.4 70.99,21.34 B19.S2
O_EXTA1  (via drill 0.61)
  Top 0.152: v42.16,71.37 53.72,59.82 53.72,54.74 54.1,54.36 54.1,48.51 67.18,35.43 67.18,29.59 69.34,27.43 70.74,27.43 B19.P2 | v44.83,79.88 44.83,80.64 43.43,82.04 40.13,82.04 29.08,93.09 29.08,115.44 24.38,120.14 22.99,120.14 21.34,121.79 A23.E2
  Bottom 0.152: v42.16,71.37 42.16,77.22 v44.83,79.88
O_EXTA2  (via drill 0.61)
  Top 0.152: v70.99,41.27 70.99,44.83 70.36,45.47 70.36,50.42 46.74,74.04 46.74,74.93 28.7,92.96 28.7,112.52 19.56,121.67 19.56,123.06 17.91,124.71 A23.D2
  Bottom 0.152: v70.99,41.27 66.42,36.7 69.34,33.78 70.74,33.78 B19.M2
O_INIT
  Top 0.152: A14.V2 132.21,80.26 132.21,79.63 137.29,74.55 137.29,74.3 137.67,73.91 137.67,72.9 141.48,69.09 141.99,69.09 156.59,54.48 159.89,54.48 170.94,43.43 170.94,40.13 172.47,38.61 178.82,38.61 186.06,31.37 186.18,31.37 187.83,29.72 187.83,29.59 188.34,29.08 191.64,29.08 196.34,24.38 196.34,22.99 197.99,21.34 B09.S2
O_IOP1  (via drill 0.61)
  Top 0.152: v136.65,110.87 140.08,107.44 145.03,107.44 148.21,104.27 154.56,104.27 159.64,99.19 161.29,99.19 204.47,56.01 207.26,56.01 B08.D2
  Bottom 0.152: v136.65,110.87 136.53,110.87 135.64,109.98 A14.K2
O_IOP2  (via drill 0.61)
  Top 0.152: v142.88,109.86 144.02,109.86 147.07,106.81 148.21,106.81 150.11,104.9 155.07,104.9 v158.37,101.6 | v156.84,97.28 157.35,97.28 193.93,60.71 193.93,60.33 206.76,47.5 206.76,46.86 206.88,46.74 206.88,45.59 209.04,43.43 209.04,42.04 210.69,40.39 B08.K2
  Bottom 0.152: v142.88,109.86 142.37,109.35 142.37,108.97 137.03,103.63 135.64,103.63 A14.M2 | v158.37,101.6 158.37,98.81 v156.84,97.28
O_IOP4  (via drill 0.61)
  Top 0.152: v176.53,45.97 v130.43,92.08 | v177.8,47.24 177.8,42.93 v178.05,42.67 | v173.61,31.75 173.61,31.11 175.64,29.08 178.44,29.08 178.69,28.83 179.71,28.83 v189.48,19.05 | v203.2,30.35 203.2,29.59 203.96,28.83 204.6,28.83 205.87,27.56 205.87,26.92 207.9,24.89 208.53,24.89 209.04,24.38 209.04,22.48 210.44,21.08 B08.S2
  Bottom 0.152: v130.43,92.08 130.68,92.33 130.68,94.23 132.84,96.39 134.24,96.39 A14.P2 | v177.8,47.24 v176.53,45.97 | v178.05,42.67 178.05,40.01 171.96,33.91 171.96,32.64 173.23,31.37 v173.61,31.75 | v189.48,19.05 189.48,19.68 191.52,21.72 193.93,21.72 194.06,21.84 194.94,21.84 202.69,29.59 202.69,29.84 v203.2,30.35
O_IRQ  (via drill 0.61)
  Top 0.152: v104.01,76.2 104.01,81.15 98.55,86.61 98.55,87.12 86.23,99.44 86.23,100.84 84.58,102.49 A18.M2
  Bottom 0.152: v104.01,76.2 76.58,48.77 77.47,47.88 77.6,47.88 78.99,46.48 83.44,46.48 B18.H2
O_LINE  (via drill 0.61)
  Top 0.152: v103.38,50.8 103.12,50.8 87.88,66.04 87.88,69.34 75.18,82.04 74.8,82.04 74.42,82.42 74.42,83.31 75.69,84.58 77.22,83.06 78.61,83.06 80.26,81.41 A18.V2
  Bottom 0.152: v103.38,50.8 103.25,50.8 86.23,33.78 84.84,33.78 B18.M2
O_MB00  (via drill 0.61)
  Top 0.152: v139.57,142.37 v175.9,142.37 | v200.15,141.22 203.2,141.22 216.92,127.51 218.31,127.51 219.96,125.86 A07.D2
  Bottom 0.152: v139.57,142.37 123.06,125.86 119.76,125.86 A15.D2 | v175.9,142.37 176.53,142.37 177.67,143.51 178.82,143.51 178.94,143.64 197.74,143.64 v200.15,141.22
O_MB01  (via drill 0.61)
  Top 0.152: v219.07,106.17 219.07,106.3 216.41,108.97 216.41,112.27 211.71,116.97 207.65,116.97 191.26,133.35 187.2,133.35 v186.82,133.73 | v146.18,98.17 144.15,98.17 126.11,116.2 126.11,116.71 124.33,118.49 124.33,119.89 122.68,121.54 A15.E2
  Bottom 0.152: v219.07,106.17 219.58,106.68 219.58,106.93 221.74,109.09 223.14,109.09 A07.K2 | v186.82,133.73 181.23,133.73 176.15,128.65 176.15,128.14 v146.18,98.17
O_MB02  (via drill 0.61)
  Top 0.152: v210.19,79.63 210.19,82.3 194.94,97.54 193.04,97.54 186.31,104.27 180.47,104.27 179.07,105.66 178.56,105.66 176.78,107.44 173.99,107.44 173.86,107.57 172.59,107.57 165.35,114.81 163.7,114.81 162.69,115.82 162.05,115.82 148.21,129.67 v139.32,129.67
  Bottom 0.152: v210.19,79.63 210.44,79.88 214.88,79.88 223.39,88.39 223.39,89.79 A07.S2 | v139.32,129.67 134.37,129.67 124.33,119.63 124.33,118.24 122.68,116.59 A15.H2
O_MB03  (via drill 0.61)
  Top 0.152: v173.48,139.19 178.56,139.19 181.99,135.76 183.26,135.76 185.17,133.86 185.55,133.86 186.44,132.97 191.13,132.97 206.5,117.6 206.5,115.82 209.04,113.28 209.04,111.89 210.69,110.24 A08.K2
  Bottom 0.152: v173.48,139.19 173.35,139.06 169.93,139.06 167.51,136.65 165.99,136.65 165.86,136.53 164.59,136.53 164.08,136.02 159.77,136.02 149.86,126.11 146.94,126.11 133.22,112.39 133.22,112.01 124.84,103.63 122.94,103.63 A15.M2
O_MB03\  (via drill 0.61)
  Top 0.152: v127,109.86 122.94,109.86 A15.K2 | v191.39,140.34 204.22,127.51 205.61,127.51 207.26,125.86 A08.D2
  Bottom 0.152: v127,109.86 127.25,109.86 147.07,129.67 152.91,129.67 159.64,136.4 160.27,136.4 163.32,139.45 166.75,139.45 168.91,141.6 176.28,141.6 177.8,143.13 178.94,143.13 179.07,143.26 188.47,143.26 v191.39,140.34
O_MB04  (via drill 0.61)
  Top 0.152: v174.62,137.79 179.45,137.79 181.86,135.38 183.13,135.38 185.04,133.48 185.42,133.48 191.39,127.51 192.91,127.51 194.56,125.86 A09.D2
  Bottom 0.152: v174.62,137.79 172.85,136.02 172.47,136.02 171.96,135.51 170.81,135.51 166.5,131.19 165.35,131.19 136.02,101.85 135.25,101.85 124.33,90.93 122.94,90.93 A15.S2
O_MB04\  (via drill 0.61)
  Top 0.152: v189.99,68.07 188.98,68.07 v185.67,71.37 | v180.34,67.18 179.58,67.18 156.21,90.55 155.57,90.55 154.56,91.57 150.11,91.57 135.13,106.55 133.86,106.55 v132.97,107.44
  Bottom 0.152: v189.99,68.07 197.36,75.44 197.99,75.44 210.69,88.14 210.69,89.79 A08.S2 | v185.67,71.37 184.53,71.37 v180.34,67.18 | v132.97,107.44 131.19,107.44 124.33,100.58 124.33,99.19 122.68,97.54 A15.P2
O_MB05  (via drill 0.61)
  Top 0.152: v150.37,53.98 123.06,81.28 123.06,81.92 122.68,82.3 122.56,82.3 122.17,82.68 120.9,81.41 119.76,81.41 A15.V2 | v192.15,94.11 193.17,94.11 194.69,92.58 196.09,92.58 197.74,90.93 A09.S2
  Bottom 0.152: v150.37,53.98 152.15,53.98 180.47,82.3 180.47,82.42 v192.15,94.11
O_MB05\  (via drill 0.61)
  Top 0.152: v169.8,133.35 172.97,133.35 194.69,111.63 196.09,111.63 197.74,109.98 A09.K2
  Bottom 0.152: v169.8,133.35 167.26,130.81 165.48,130.81 136.14,101.47 135.38,101.47 121.67,87.76 119.76,87.76 A15.T2
O_MB06  (via drill 0.61)
  Top 0.152: v183.77,108.58 182.5,108.58 170.56,120.52 160.15,120.52 159.77,120.9 157.99,120.9 148.46,130.43 143.38,130.43 142.24,131.57 139.95,131.57 138.68,132.84 v121.79,132.84
  Bottom 0.152: v183.77,108.58 184.28,109.09 185.04,109.09 A10.K2 | v121.79,132.84 113.28,124.33 111.89,124.33 110.24,122.68 A16.E2
O_MB06\
  Top 0.152: A16.D2 105.92,126.11 105.92,130.56 105.28,131.19 105.28,134.49 114.43,143.64 133.73,143.64 138.05,139.32 170.43,139.32 180.47,129.29 180.47,127.76 182.12,126.11 A10.D2
O_MB07  (via drill 0.61)
  Top 0.152: v115.82,107.95 114.68,109.09 110.24,109.09 A16.K2 | v151.76,136.53 157.1,136.53 166.12,127.51 167.51,127.51 169.16,125.86 A11.D2
  Bottom 0.152: v115.82,107.95 116.2,107.95 129.54,121.28 131.32,121.28 134.62,124.59 135.13,124.59 137.41,126.87 142.11,126.87 v151.76,136.53
O_MB07\
  Top 0.152: A10.S2 185.04,90.93 183.26,90.93 156.08,118.11 153.92,118.11 147.7,124.33 147.19,124.33 145.03,126.49 141.35,126.49 137.79,130.05 108.71,130.05 108.33,130.43 107.57,130.43 106.3,129.16 106.3,127.13 107.44,125.98 107.44,118.24 109.09,116.59 A16.H2
O_MB08  (via drill 0.61)
  Top 0.152: v140.84,125.09 165.61,100.33 165.61,96.27 170.94,90.93 172.34,90.93 A11.S2
  Bottom 0.152: v140.84,125.09 139.45,125.09 138.68,124.33 135.89,124.33 135.38,123.83 134.87,123.83 111.63,100.58 111.63,99.19 109.98,97.54 A16.P2
O_MB08\  (via drill 0.61)
  Top 0.152: v131.57,78.61 109.98,100.2 109.98,102.49 A16.M2 | v169.16,114.81 169.42,114.81 170.94,113.28 170.94,111.89 172.59,110.24 A11.K2
  Bottom 0.152: v131.57,78.61 145.92,92.96 145.92,93.22 153.42,100.71 153.42,100.97 155.07,102.62 155.07,105.41 155.57,105.92 155.57,106.43 159.77,110.62 164.97,110.62 v169.16,114.81
O_MB09  (via drill 0.61)
  Top 0.152: v116.33,87.88 114.17,90.04 110.24,90.04 A16.S2
  Bottom 0.152: v116.33,87.88 116.33,88.14 148.97,120.78 150.88,120.78 153.42,123.32 154.81,123.32 156.46,124.97 A12.D2
O_MB10  (via drill 0.61)
  Top 0.152: v123.83,73.53 114.3,83.06 108.97,83.06 106.81,85.22 106.81,86.61 A16.T2
  Bottom 0.152: v123.83,73.53 127.64,73.53 149.86,95.76 149.86,96.52 153.8,100.46 153.8,100.84 155.45,102.49 155.45,103 158.24,105.79 158.24,107.19 159.89,108.84 A12.K2
O_MB11  (via drill 0.61)
  Top 0.152: v120.78,67.69 107.95,80.52 107.06,80.52 A16.V2 | v153.67,93.6 155.57,93.6 156.59,92.58 157.99,92.58 159.64,90.93 A12.S2
  Bottom 0.152: v120.78,67.69 123.19,67.69 147.07,91.57 151.64,91.57 v153.67,93.6
O_MBINCR  (via drill 0.61)
  Top 0.152: v50.16,79.5 63.63,66.04 63.63,64.39 68.2,59.82 68.2,59.44 70.99,56.64 70.99,53.09 B19.E2
  Bottom 0.152: v50.16,79.5 50.16,80.26 50.29,80.39 50.29,83.69 51.82,85.22 53.21,85.22 54.86,86.87 A20.T2
O_RUN  (via drill 0.61)
  Top 0.152: v100.84,75.95 86.74,90.04 84.84,90.04 A18.S2 | v110.24,76.96 110.36,76.96 120.4,66.93 122.05,66.93 129.67,59.31 129.67,57.91 131.32,56.26 B14.D2
  Bottom 0.152: v100.84,75.95 102.62,75.95 103.63,76.96 v110.24,76.96
O_SKIP  (via drill 0.61)
  Top 0.152: v101.6,71.63 101.6,76.71 95,83.31 95,83.82 85.85,92.96 85.85,93.47 79.88,99.44 79.88,106.93 83.19,110.24 83.44,109.98 A18.K2
  Bottom 0.152: v101.6,71.63 94.61,64.64 93.6,64.64 84.58,55.63 84.58,53.09 B18.E2
O_TS1  (via drill 0.61)
  Top 0.152: v130.94,85.22 134.37,81.79 135.64,81.79 v148.84,68.58 | v160.27,77.47 164.59,77.47 196.72,45.34 196.72,42.16 198.5,40.39 B09.K2
  Bottom 0.152: v130.94,85.22 131.32,85.6 131.32,86.61 A14.T2 | v148.84,68.58 150.5,68.58 152.91,70.99 153.8,70.99 v160.27,77.47
O_TS3  (via drill 0.61)
  Top 0.152: v164.21,63.88 138.05,90.04 135.64,90.04 A14.S2 | v175.77,73.66 178.82,73.66 187.2,65.28 187.2,65.15 189.36,62.99 189.48,62.99 189.99,62.48 189.99,60.33 190.12,60.2 190.12,59.05 191.52,57.66 192.91,57.66 194.56,56.01 B09.D2
  Bottom 0.152: v164.21,63.88 164.21,64.26 166.12,66.17 168.28,66.17 v175.77,73.66
O_TT_INST  (via drill 0.61)
  Top 0.152: v131.06,39.37 122.3,48.13 118.49,48.13 104.52,62.1 104.14,62.1 103.76,62.48 103.76,63.12 102.87,64.01 102.62,64.01 82.3,84.33 82.3,84.84 81.41,85.72 81.41,86.61 A18.T2
  Bottom 0.152: v131.06,39.37 134.24,39.37 B14.K2
O_WCOV  (via drill 0.61)
  Top 0.152: v92.84,38.48 91.57,39.75 91.57,40.26 72.9,58.93 72.9,59.44 71.12,61.21 71.12,61.85 52.7,80.26 52.7,81.53 37.85,96.39 34.04,96.39 A22.P2 | v110.62,49.91 110.62,49.66 118.49,41.78 119.89,41.78 121.54,40.13 B15.K2
  Bottom 0.152: v92.84,38.48 99.19,38.48 v110.62,49.91
VCC  (via drill 0.61)
  Top 0.381: v228.35,136.4 234.82,136.4 235.84,135.38 A06.A2 | A09.A2 197.74,135.38 197.61,135.38 191.77,141.22 185.55,141.22 182.12,137.79 185.04,134.87 A10.A2 | v207.52,138.05 210.19,135.38 210.44,135.38 A08.A2 | v218.06,140.59 223.14,135.51 223.14,135.38 A07.A2 | v90.68,68.58 93.09,68.58 96.14,65.53 B17.A2 | v68.96,66.29 69.98,66.29 70.74,65.53 B19.A2 | v25.4,69.34 28.83,69.34 32.64,65.53 B22.A2 | v39.75,68.96 43.18,65.53 45.34,65.53 B21.A2 | v52.07,69.85 56.39,65.53 58.04,65.53 B20.A2 | v79.5,69.34 83.31,65.53 83.44,65.53 B18.A2 | v191.13,70.48 192.79,70.48 197.74,65.53 B09.A2 | v215.65,66.55 222.12,66.55 223.14,65.53 B07.A2 | v229.87,71.25 235.59,65.53 235.84,65.53 B06.A2 | v205.1,70.36 205.61,70.36 210.44,65.53 B08.A2 | v116.2,61.98 113.54,64.64 110.24,64.64 B16.A2 108.84,65.53 104.27,70.1 v102.87,70.1 | v129.29,68.33 132.08,65.53 134.24,65.53 B14.A2 | v142.62,69.6 146.69,65.53 146.94,65.53 B13.A2 | v154.43,70.48 159.38,65.53 159.64,65.53 B12.A2 | v167.39,70.36 172.21,65.53 172.34,65.53 B11.A2 | v179.07,70.74 184.28,65.53 185.04,65.53 B10.A2
  Bottom 0.381: v228.35,136.4 227.33,135.38 224.54,135.38 A07.A2 223.14,134.75 220.98,134.75 220.47,134.24 220.47,133.35 219.46,132.33 219.46,130.81 221.36,128.91 166.5,74.04 166.12,74.04 159.26,67.18 159.26,66.42 159.89,65.79 B12.A2 161.04,65.53 165.86,70.36 v167.39,70.36 | 175.9,137.79 175.01,138.68 174.24,138.68 171.7,136.14 166.12,136.14 165.35,135.38 161.04,135.38 A12.A2 | 175.9,137.79 A11.A2 | A10.A2 185.29,135.64 185.29,138.43 183.64,140.08 179.58,140.08 179.2,139.7 177.8,139.7 175.9,137.79 | v207.52,138.05 201.8,138.05 199.14,135.38 A09.A2 | v218.06,140.59 216.79,140.59 A08.A2 | v90.68,68.58 87.63,65.53 84.84,65.53 B18.A2 | v68.96,66.29 64.52,66.29 63.75,65.53 59.44,65.53 B20.A2 | v25.4,69.34 21.59,65.53 21.34,65.53 B23.A2 | v39.75,68.96 37.47,68.96 34.04,65.53 B22.A2 | v52.07,69.85 51.05,69.85 46.74,65.53 B21.A2 | v79.5,69.34 75.95,69.34 72.14,65.53 B19.A2 | v191.13,70.48 B10.A2 | v215.65,66.55 215.52,66.42 212.72,66.42 211.84,65.53 B08.A2 | v229.87,71.25 229.74,71.25 224.28,65.79 B07.A2 | v205.1,70.36 200.28,65.53 199.14,65.53 B09.A2 | v116.2,61.98 117.35,61.98 118.49,63.12 120.02,63.12 121.54,64.64 B15.A2 122.94,65.53 125.73,68.33 v129.29,68.33 | v142.62,69.6 139.7,69.6 135.64,65.53 B14.A2 | v154.43,70.48 153.03,70.48 B13.A2 | v179.07,70.74 178.94,70.74 173.74,65.53 B11.A2 | v102.87,70.1 98.3,65.53 97.54,65.53 B17.A2

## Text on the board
Bottom: VRS | DW08A | DW08A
